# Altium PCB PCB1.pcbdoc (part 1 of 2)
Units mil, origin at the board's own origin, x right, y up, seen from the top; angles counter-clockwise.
Board outline 2869.57 x 2682.86 mil, 2 copper layers (Top Layer, Bottom Layer); 61 components, 43 nets, 230 pads, 47 vias.
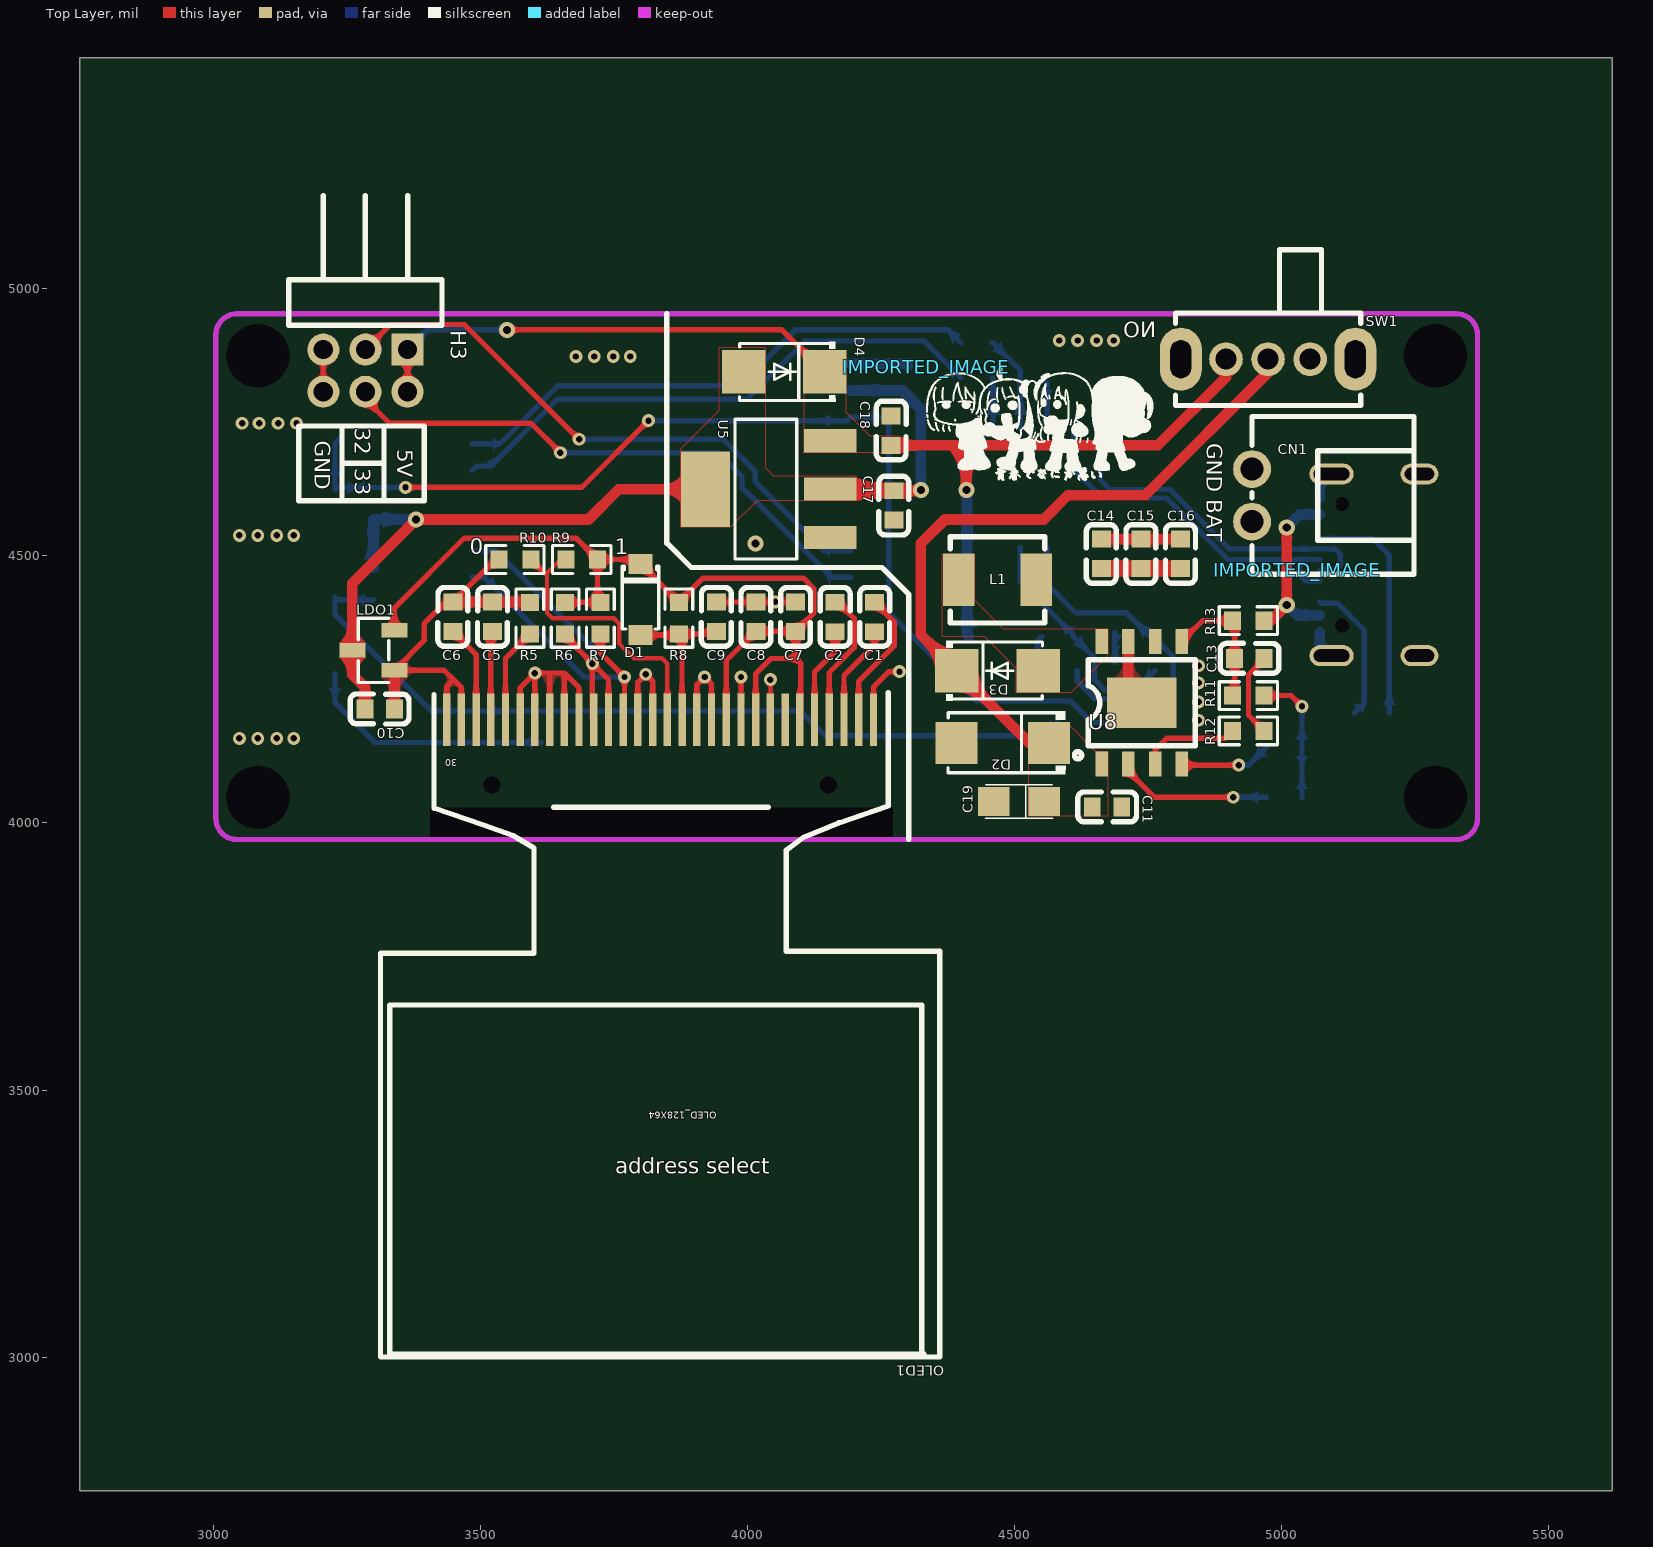
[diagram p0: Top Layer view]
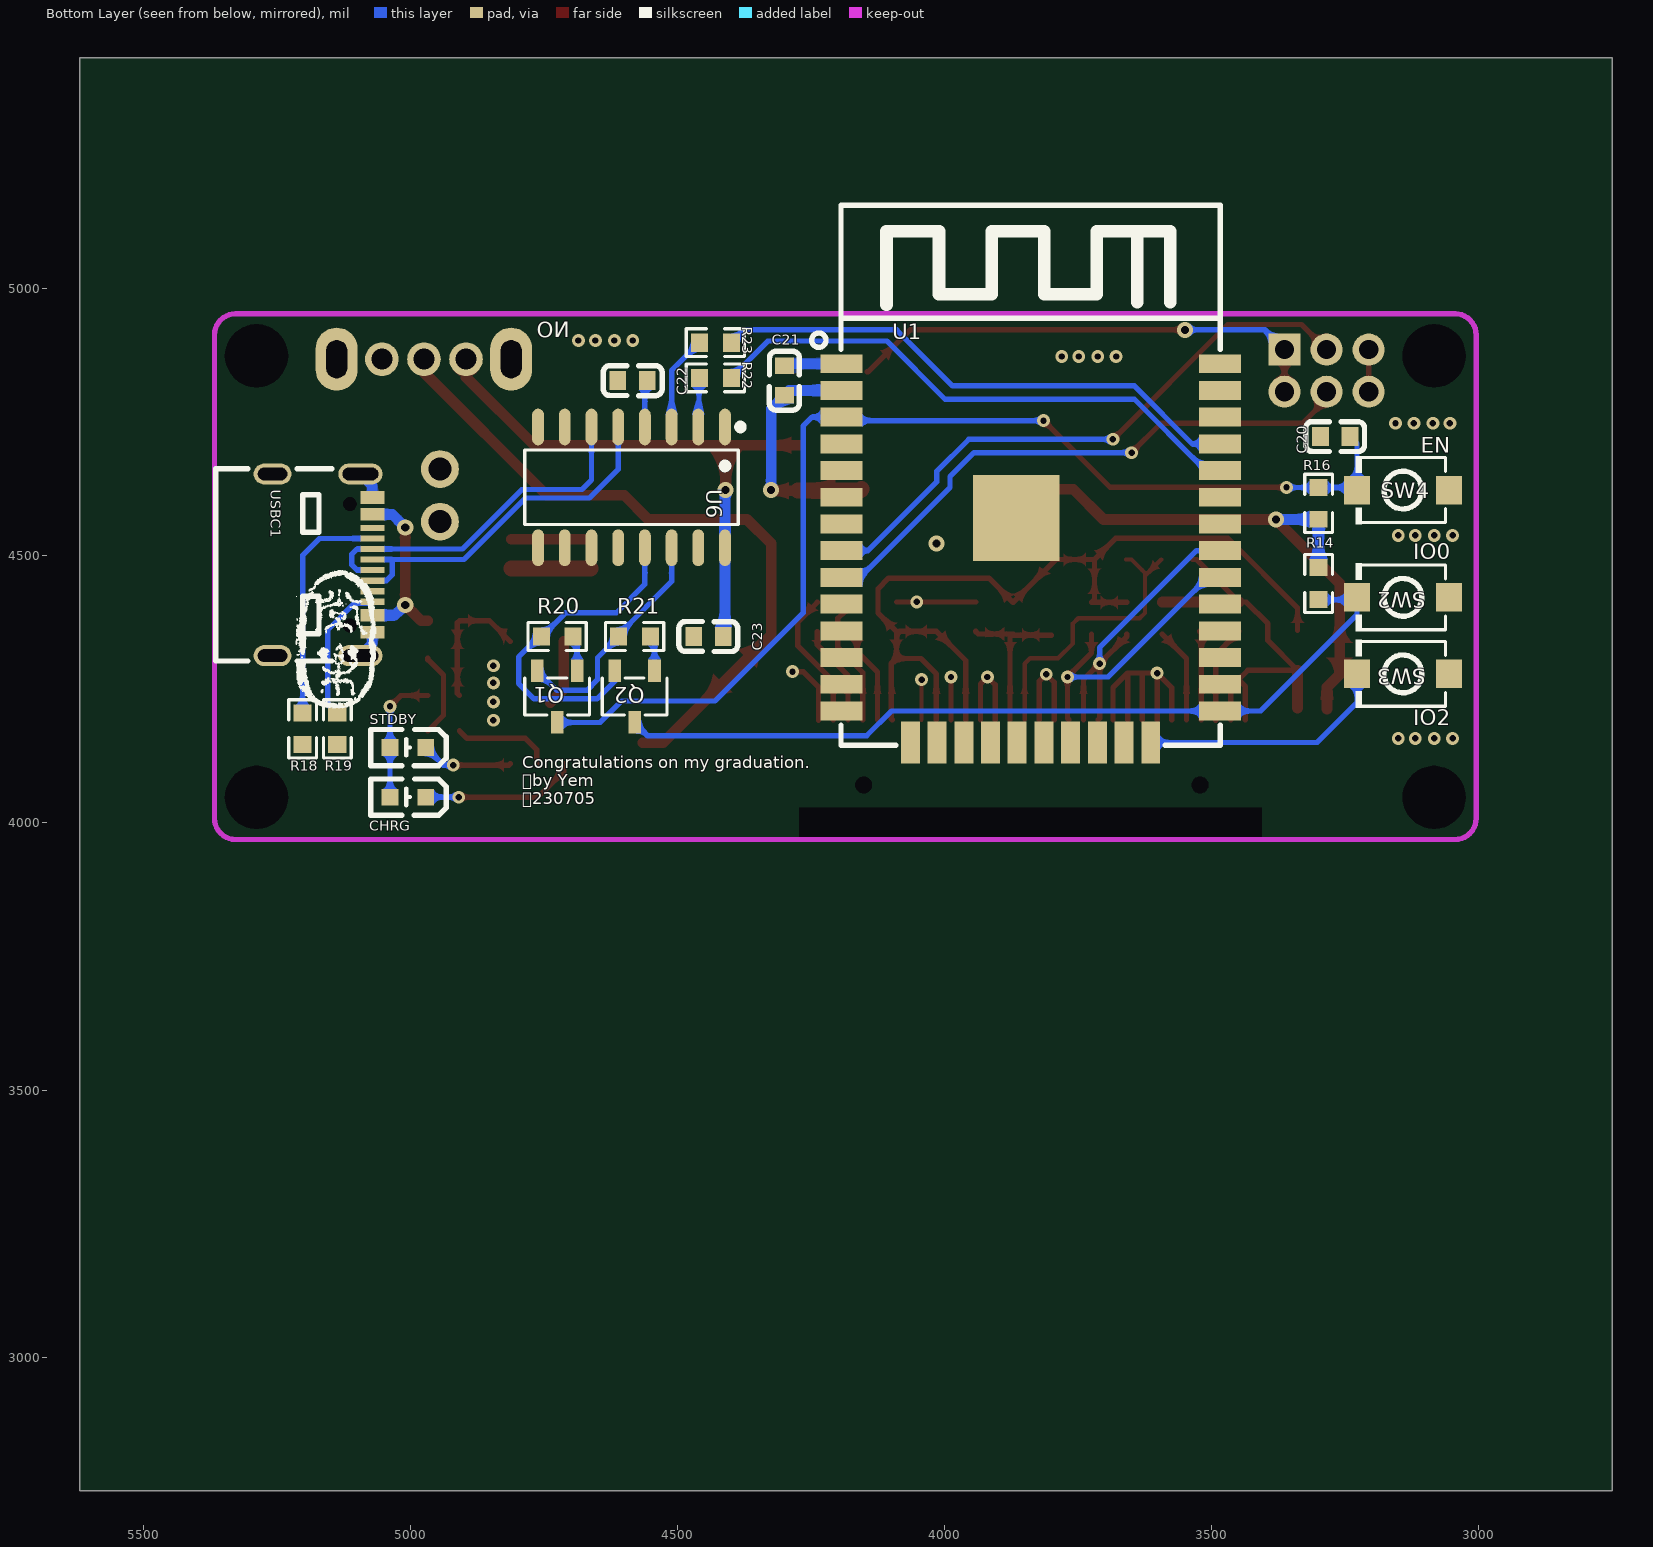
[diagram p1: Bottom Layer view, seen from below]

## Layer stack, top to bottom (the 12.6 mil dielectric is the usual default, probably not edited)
Top Layer: signal copper (thickness not stored)
Dielectric: dielectric 12.6, FR-4, Dk 4.8
Bottom Layer: signal copper (thickness not stored)

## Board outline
5619.57,2750 2750,2750 2750,5432.86 5619.57,5432.86
cut-out: 3142.8,4874.59 ccw(c3083.74,4874.59) 3024.69,4874.59 ccw(c3083.74,4874.59)
cut-out: 5347.52,4874.59 ccw(c5288.46,4874.59) 5229.41,4874.59 ccw(c5288.46,4874.59)
cut-out: 5347.52,4047.81 ccw(c5288.46,4047.81) 5229.41,4047.81 ccw(c5288.46,4047.81)
cut-out: 3142.8,4047.81 ccw(c3083.74,4047.81) 3024.69,4047.81 ccw(c3083.74,4047.81)
cut-out: 3406.18,3969.07 4272.32,3969.07 4272.32,4028.13 3406.18,4028.13

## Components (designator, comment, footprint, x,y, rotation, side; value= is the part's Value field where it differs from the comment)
C1 "1uf" C0603 4238.39,4385.65 r270 top
C2 "CAP_0603" C0603 4164.27,4385.65 r270 top
C5 "4.7uf" C0603 3523.01,4386.26 r90 top
C6 "2.2uf" C0603 3448.89,4386.26 r90 top
C7 "1uf" C0603 4090.36,4386.26 r90 top
C8 "1uf" C0603 4016.24,4386.26 r90 top
C9 "4.7uf" C0603 3942.12,4386.26 r90 top
C10 "1uf" C0603 3311.81,4213.33 r0 top
C11 "CAP_0603" C0603 4673.48,4030.14 r180 top
C13 "10uf" C0603 4939.99,4308.33 r180 top
C14 "0.1uf" C0603 4662.83,4503.89 r90 top
C15 "22uf" C0603 4736.95,4503.89 r90 top
C16 "22uf" C0603 4811.07,4503.89 r90 top
C17 "CAP_0603" C0603 4274.32,4594.53 r90 top
C18 "CAP_0603" C0603 4269.32,4734.53 r270 top
C19 "TC212A476K010Y" CASE-A_3216 4508.48,4040.14 r180 top
C20 "CAP_0603" C0603 3268.67,4723.33 r180 bottom
C21 "CAP_0603" C0603 4300,4828.33 r90 bottom
C22 "0.1uf" C0603 4584.42,4828.33 r0 bottom
C23 "CAP_0603" C0603 4442.28,4348.98 r180 bottom
CHRG "CHRG" LED0603-R-RD_GREEN 5005,4048.33 r0 bottom
CN1 "HX25003-2WAP" CONN-TH_2P-P2.50_HX25003-2WAP 4945,4613.33 r90 top
D1 "1N4148W_C2099" SOD-123_L2.8-W1.8-LS3.7-RD 3800,4418.33 r270 top
D2 "SMAJ6.0A_C223993" SMA_L4.3-W2.6-LS5.2-RD 4478.48,4150.14 r180 top
D3 "SS34-MS" DO-214AC_L4.3-W2.7-LS5.0-RD 4468.48,4285.14 r0 top
D4 "SS34-MS" DO-214AC_L4.3-W2.7-LS5.0-RD 4069.32,4844.53 r180 top
H3 "PZ200-2-03-W" HDR-TH_6P-P2.00-H-M-R2-C3-S2.00-W9.8 3285,4846.88 r180 top
IMPORTED_IMAGE "IMPORTED_IMAGE" IMPORTED_IMAGE 5030,4473.33 r0 top
IMPORTED_IMAGE "IMPORTED_IMAGE" IMPORTED_IMAGE 4335,4853.33 r0 top
L1 "TMPC0402HP-100MG-Z02" IND-SMD_L4.5-W4.1_TMPA0402SP 4468.48,4455.14 r0 top
LDO1 "SC662K-3.3V" SOT-23-3_L2.9-W1.3-P1.90-LS2.4-BR 3300,4323.33 r0 top
OLED1 "QG-2864KSWEG01" OLED-SMD_QG-2864KSWEG01 3836.77,4193.17 r180 top
Q1 "S8050_C105433" SOT-23-3_L2.9-W1.6-P1.90-LS2.8-BR 4725.66,4236.77 r90 bottom
Q2 "S8050_C105433" SOT-23-3_L2.9-W1.6-P1.90-LS2.8-BR 4580.66,4236.77 r90 bottom
R5 "910k" R0603 3592.97,4383.45 r270 top
R6 "4.7k" R0603 3658.98,4383.45 r270 top
R7 "4.7k" R0603 3725,4383.45 r270 top
R8 "4.7k" R0603 3871.94,4383.45 r90 top
R9 "4.7k" R0603 3690,4493.33 r0 top
R10 "4.7k" R0603 3565,4493.33 r0 top
R11 "1k" R0603 4938.02,4238.53 r180 top
R12 "3k" R0603 4938.02,4172.51 r180 top
R13 "0.3" R0603 4938.02,4378.66 r0 top
R14 "Res_0603" R0603 3300,4448.33 r90 bottom
R16 "Res_0603" R0603 3300,4598.33 r270 bottom
R18 "5K1" R0603 5202.18,4176.23 r90 bottom
R19 "5K1" R0603 5137.18,4176.23 r90 bottom
R20 "10k" R0603 4725.66,4349.09 r180 bottom
R21 "10k" R0603 4580.66,4349.09 r180 bottom
R22 "120" R0603 4429.22,4833.23 r0 bottom
R23 "120" R0603 4429.22,4899.24 r0 bottom
STDBY "TLMG1100-GS08" LED0603-R-RD_GREEN 5005,4141.14 r0 bottom
SW1 "SK12D07VG3" SW-TH_SK12D07VG3 4975,4868.33 r180 top
SW2 "TS-1088R-02026" SW-SMD_L3.9-W3.0-P4.45 3142.01,4422.43 r0 bottom
SW3 "TS-1088R-02026" SW-SMD_L3.9-W3.0-P4.45 3142.01,4279.12 r0 bottom
SW4 "TS-1088R-02026" SW-SMD_L3.9-W3.0-P4.45 3142.01,4623.33 r0 bottom
U1 "ESP32-WROOM-32-N4" WIFIM-SMD_ESP32-WROOM-32-N4 3839.25,4505.26 r180 bottom
U5 "AMS1117-3.3_C6186" SOT-223-3_L6.5-W3.4-P2.30-LS7.0-BR 4038.62,4625.04 r0 top
U6 "CH340C" SOP-16_L10.0-W3.9-P1.27-LS6.0-BL 4586.29,4628.33 r0 bottom
U8 "TP5400" ESOP-8_L4.9-W3.9-P1.27-LS6.0-BL-EP 4738.48,4225.14 r0 top
USBC1 "MC-311D" USB-C-SMD_MC-311D 5165,4483.33 r270 bottom

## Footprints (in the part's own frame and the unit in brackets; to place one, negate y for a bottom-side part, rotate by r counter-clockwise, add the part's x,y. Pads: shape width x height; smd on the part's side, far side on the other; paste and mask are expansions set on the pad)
C0603 [mm]
  rect 0.8x0.9 smd paste+0 mask+0.051: 1(-0.7,0) 2(0.7,0)
  silkscreen extent -1.41,-0.71 1.39,0.72
CASE-A_3216 [mil]
  rect 59.05x53.5 smd paste+0 mask+2: 1(-47.24,0) 2(47.24,0)
  silkscreen extent -63,-32 63,32
CONN-TH_2P-P2.50_HX25003-2WAP [mm]
  round 1.8 hole 1.1 paste+0 mask+0.051: 1(-1.25,0) 2(1.25,0)
  silkscreen extent -3.75,-7.7 3.75,0
DO-214AC_L4.3-W2.7-LS5.0-RD [mm]
  rect 2.07x2.06 smd paste+0 mask+0.051: 1(-1.929,0) 2(1.929,0)
  silkscreen extent -2.43,-1.43 2.14,1.43
ESOP-8_L4.9-W3.9-P1.27-LS6.0-BL-EP [mm]
  rect 0.6x1.2 smd paste+0 mask+0.051: 1(-1.905,-2.908) 2(-0.635,-2.908) 3(0.635,-2.908) 4(1.905,-2.908) 5(1.905,2.908) 6(0.635,2.908) 7(-0.635,2.908) 8(-1.905,2.908)
  rect 3.3x2.4 smd paste+0 mask+0.051: 9(0,0)
  silkscreen extent -3.2,-2.67 2.55,2.05
HDR-TH_6P-P2.00-H-M-R2-C3-S2.00-W9.8 [mil]
  rect 60x60 hole 36 mask+2: 1(-78.74,-39.37)
  round 60 hole 36 mask+2: 2(-78.74,39.37) 3(0,-39.37) 4(0,39.37) 5(78.74,-39.37) 6(78.74,39.37)
  silkscreen extent -143,-327 143,-85
IMPORTED_IMAGE [mil]
IND-SMD_L4.5-W4.1_TMPA0402SP [mm]
  rect 1.5x2.5 smd paste+0 mask+0.051: 1(-1.85,0) 2(1.85,0)
  silkscreen extent -2.25,-2.05 2.25,2.05
LED0603-R-RD_GREEN [mm]
  rect 0.8x0.8 smd paste+0 mask+0.051: 1(0.851,0) 2(-0.851,0)
  silkscreen extent -1.82,-0.86 1.77,0.86
OLED-SMD_QG-2864KSWEG01 [mil]
  rect 13.8x98.4 smd paste+0 mask+1.97: 1(-399.57,-0.09) 2(-371.81,-0.01) 3(-344.25,-0.01) 4(-316.69,-0.01) 5(-289.13,-0.01) 6(-261.57,-0.01) 7(-234.01,-0.01) 8(-206.46,-0.01) 9(-178.9,-0.01) 10(-151.34,-0.01) 11(-123.78,-0.01) 12(-96.22,-0.01) 13(-68.66,-0.01) 14(-41.1,-0.01) 15(-13.54,-0.01) 16(14.02,-0.01) 17(41.58,-0.01) 18(69.13,-0.01) 19(96.69,-0.01) 20(124.25,-0.01) 21(151.81,-0.01) 22(179.37,-0.01) 23(206.93,-0.01) 24(234.49,-0.01) 25(262.05,-0.01) 26(289.61,-0.01) 27(317.17,-0.01) 28(344.53,0.05) 29(372.05,0.09) 30(399.57,0.09)
  Multi-Layer board cut-out: -330.71,122.05 -329.15,115.22 -324.78,109.74 -318.46,106.7 -311.46,106.7 -305.14,109.74 -300.77,115.22 -299.21,122.05 -299.21,122.05 -300.77,128.88 -305.14,134.36 -311.46,137.4 -318.46,137.4 -324.78,134.36 -329.15,128.88 -330.71,122.05
  Multi-Layer board cut-out: 299.21,122.05 300.77,115.22 305.14,109.74 311.46,106.7 318.46,106.7 324.78,109.74 329.15,115.22 330.71,122.05 330.71,122.05 329.15,128.88 324.78,134.36 318.46,137.4 311.46,137.4 305.14,134.36 300.77,128.88 299.21,122.05
  silkscreen extent -524,-51 524,1193
R0603 [mil]
  rect 31.75x34.02 smd paste-3937.01 mask+2: 1(-29.66,0) 2(29.66,0)
  silkscreen extent -55,-26 55,26
SMA_L4.3-W2.6-LS5.2-RD [mm]
  rect 2x2 smd paste+0 mask+0.051: 1(-2.2,0) 2(2.2,0)
  silkscreen extent -2.98,-1.5 2.6,1.5
SOD-123_L2.8-W1.8-LS3.7-RD [mm]
  rect 0.95x1.15 smd paste+0 mask+0.051: 1(-1.692,0) 2(1.692,0)
  silkscreen extent -1.58,-0.87 1.41,0.87
SOP-16_L10.0-W3.9-P1.27-LS6.0-BL [mm]
  oval 0.56x1.745 smd paste+0 mask+0.051: 1(-4.445,-2.872) 2(-3.175,-2.872) 3(-1.905,-2.872) 4(-0.635,-2.872) 5(0.635,-2.872) 6(1.905,-2.872) 7(3.175,-2.872) 8(4.445,-2.872) 9(4.445,2.872) 10(3.175,2.872) 11(1.905,2.872) 12(0.635,2.872) 13(-0.635,2.872) 14(-1.905,2.872) 15(-3.175,2.872) 16(-4.445,2.872)
  silkscreen extent -5.33,-3.02 5.08,1.77
SOT-23-3_L2.9-W1.3-P1.90-LS2.4-BR [mm]
  rect 1.25x0.7 smd paste+0 mask+0.051: 1(1,-0.95) 2(1,0.95) 3(-1,0)
  silkscreen extent -0.73,-1.53 0.73,1.53
SOT-23-3_L2.9-W1.6-P1.90-LS2.8-BR [mm]
  rect 1.07x0.6 smd paste+0 mask+0.051: 1(1.235,-0.95) 2(1.235,0.95) 3(-1.235,0)
  silkscreen extent -0.88,-1.54 0.88,1.54
SOT-223-3_L6.5-W3.4-P2.30-LS7.0-BR [mm]
  rect 2.5x1.1 smd paste+0 mask+0.051: 1(2.97,-2.3) 2(2.97,0) 3(2.97,2.3)
  rect 2.34x3.6 smd paste+0 mask+0.051: 4(-2.97,0)
  silkscreen extent -1.57,-3.33 1.37,3.33
SW-SMD_L3.9-W3.0-P4.45 [mm]
  rect 1.23x1.36 smd paste+0 mask+0.051: 1(-2.185,0) 2(2.185,0)
  silkscreen extent -2.03,-1.62 2.25,1.62
SW-TH_SK12D07VG3 [mm]
  round 1.6 hole 1 paste+0 mask+0.051: 1(-2,0) 2(0,0) 3(2,0)
  oval 2x3 hole 1 slot 1.8 at 90 deg paste+0 mask+0.051: 4(4.15,0) 5(-4.15,0)
  silkscreen extent -4.4,-5.2 4.4,2.2
USB-C-SMD_MC-311D [mm]
  oval 1x2.1 hole 0.6 slot 1.7 at 90 deg paste+0 mask+0.05: 1(-4.32,1.808) 4(4.32,1.807)
  oval 1x1.8 hole 0.6 slot 1.4 at 90 deg paste+0 mask+0.05: 2(-4.32,-2.372) 3(4.32,-2.373)
  rect 0.6x1.15 smd paste-100 mask+0.05: A1-B12(-3.2,2.372) A4-B9(-2.4,2.372) B1-A12(3.2,2.372) B4-A9(2.4,2.372)
  rect 0.3x1.15 smd paste-100 mask+0.05: A5(-1.25,2.372) A6(-0.25,2.372) A7(0.25,2.372) A8(1.25,2.372) B5(1.75,2.372) B6(0.75,2.372) B7(-0.75,2.372) B8(-1.75,2.372)
  Multi-Layer board cut-out: 2.89,0.982 2.749,1.015 2.636,1.105 2.573,1.235 2.573,1.38 2.636,1.51 2.749,1.6 2.89,1.632 2.89,1.632 3.031,1.6 3.144,1.51 3.207,1.38 3.207,1.235 3.144,1.105 3.031,1.015 2.89,0.982
  Multi-Layer board cut-out: -2.89,0.982 -3.031,1.015 -3.144,1.105 -3.207,1.235 -3.207,1.38 -3.144,1.51 -3.031,1.6 -2.89,1.632 -2.89,1.632 -2.749,1.6 -2.636,1.51 -2.573,1.38 -2.573,1.235 -2.636,1.105 -2.749,1.015 -2.89,0.982
  silkscreen extent -4.57,-5.08 4.57,0.44
WIFIM-SMD_ESP32-WROOM-32-N4 [mm]
  rect 2x0.9 smd paste+0 mask+0.05: 1(-9,9.005) 2(-9,7.735) 3(-9,6.465) 4(-9,5.195) 5(-9,3.925) 6(-9,2.655) 7(-9,1.385) 8(-9,0.115) 9(-9,-1.155) 10(-9,-2.425) 11(-9,-3.695) 12(-9,-4.965) 13(-9,-6.235) 14(-9,-7.505) 25(9,-7.505) 26(9,-6.235) 27(9,-4.965) 28(9,-3.695) 29(9,-2.425) 30(9,-1.155) 31(9,0.115) 32(9,1.385) 33(9,2.655) 34(9,3.925) 35(9,5.195) 36(9,6.465) 37(9,7.735) 38(9,9.005)
  rect 0.9x2 smd paste+0 mask+0.05: 15(-5.715,-9.005) 16(-4.445,-9.005) 17(-3.175,-9.005) 18(-1.905,-9.005) 19(-0.635,-9.005) 20(0.635,-9.005) 21(1.905,-9.005) 22(3.175,-9.005) 23(4.445,-9.005) 24(5.715,-9.005)
  rect 4.1x4.1 smd paste+0 mask+0.05: 39(-0.68,1.665)
  silkscreen extent -10.41,-9.13 9.02,16.54

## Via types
v1: diameter 24, hole 12, Top Layer to Bottom Layer, 40 vias
v2: diameter 30, hole 15, Top Layer to Bottom Layer, 7 vias

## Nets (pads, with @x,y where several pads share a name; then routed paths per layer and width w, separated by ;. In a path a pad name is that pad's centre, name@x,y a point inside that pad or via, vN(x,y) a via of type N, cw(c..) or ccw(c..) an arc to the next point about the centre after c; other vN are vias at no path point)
3V3: C10.1 C17.2 C21.1 D4.2 LDO1.3 R14.2 R16.2 U1.2 U5.2 U5.4 | length 1619.4
  Top Layer w20: C10.1@3284.25,4213.33 3284.25,4254.08 3260.63,4277.7 LDO1.3@3260.63,4323.33 3260.63,4448.96 v2(3380,4568.33) 3702.75,4568.33 3759.47,4625.04 U5.4@3921.69,4625.04 ; C17.2@4274.32,4622.09 4323.77,4622.09 v2(4325,4623.33)
  Top Layer w30: U5.2@4155.55,4625.04 4158.49,4622.09 C17.2@4274.32,4622.09
  Bottom Layer w20: R14.2@3300,4477.99 R16.2@3300,4568.67 3300.34,4568.33 v2(3380,4568.33) ; U1.2@4193.58,4809.79 4290.98,4809.79 C21.1@4300,4800.77 4325,4775.77 v2(4325,4623.33)
$1N1215: C1.1 OLED1.2 | length 262.4
  Top Layer w10: OLED1.2@4208.58,4193.49 4208.58,4265 4275,4331.42 4275,4376.6 C1.1@4238.39,4413.21
$1N1238: C2.1 OLED1.4 | length 257.2
  Top Layer w10: OLED1.4@4153.46,4193.49 4153.46,4281.79 4200,4328.33 4200,4383.33 4170.12,4413.21 C2.1@4164.27,4413.21
$1N1393: C1.2 OLED1.3 | length 188.4
  Top Layer w10: OLED1.3@4181.02,4193.49 4181.02,4275.72 4238.39,4333.09 C1.2@4238.39,4358.09
$1N1397: C2.2 OLED1.5 | length 180.5
  Top Layer w10: OLED1.5@4125.9,4193.49 4125.9,4282.51 4164.27,4320.88 C2.2@4164.27,4358.09
$1N1534: OLED1.26 R5.2 | length 179.3
  Top Layer w10: OLED1.26@3547.16,4193.49 3547.16,4307.99 R5.2@3592.97,4353.79
$1N1817: C5.1 OLED1.27 | length 166.6
  Top Layer w10: OLED1.27@3519.6,4193.49 3519.6,4355.29 C5.1@3523.01,4358.7
$1N1822: C6.1 OLED1.28 | length 184.2
  Top Layer w10: C6.1@3448.89,4358.7 3492.24,4315.34 OLED1.28@3492.24,4192.49
$1N3071: C9.1 D1.2 OLED1.14 R8.1 | length 307.8
  Top Layer w10: D1.2@3800,4351.7 3869.84,4351.7 R8.1@3871.94,4353.79 ; OLED1.14@3877.87,4193.49 3877.87,4347.86 R8.1@3871.94,4353.79 ; C9.1@3942.12,4358.7 3937.21,4353.79 R8.1@3871.94,4353.79
$1N3221: OLED1.15 R9.1 R10.2 | length 554.8
  Top Layer w8: R10.2@3594.66,4493.33 3625,4462.99 ; R9.1@3660.34,4493.33 3650.34,4493.33 3625,4467.99 3625,4462.99 ; OLED1.15@3850.31,4193.18 3850.31,4298.01 3840,4308.33 3787.89,4308.33 3760,4336.22 3760,4373.33 3750,4383.33 3635,4383.33 3625,4393.33 3625,4462.99
$1N4369: CHRG.2 U8.2 | length 292.1
  Top Layer w10: U8.2@4713.48,4110.64 4713.48,4096.5 4761.65,4048.33 v1(4910,4048.33)
  Bottom Layer w10: v1(4910,4048.33) CHRG.2@4971.5,4048.33
$1N4372: STDBY.2 U8.4 | length 172.6
  Top Layer w10: U8.4@4813.48,4110.64 4815.79,4108.33 v1(4920,4108.33)
  Bottom Layer w10: v1(4920,4108.33) 4938.69,4108.33 STDBY.2@4971.5,4141.14
$1N4419: CHRG.1 R11.1 STDBY.1 | length 249.2
  Top Layer w10: R11.1@4967.68,4238.53 5018.3,4238.53 v1(5038.5,4218.33)
  Bottom Layer w10: CHRG.1@5038.5,4048.33 STDBY.1@5038.5,4141.14 v1(5038.5,4218.33)
$1N4498: D3.2 L1.1 U8.8
$1N9366: R18.2 USBC1.A5 | length 438.8
  Bottom Layer w10: USBC1.A5@5071.6,4532.54 5170.79,4532.54 5202.18,4501.15 R18.2@5202.18,4205.89
$1N9477: C22.1 U6.4 | length 88.7
  Bottom Layer w10: C22.1@4556.86,4828.33 4561.29,4823.89 U6.4@4561.29,4741.42
$1N9678: Q2.1 R21.2 | length 66.9
  Bottom Layer w10: Q2.1@4543.26,4285.39 4543.26,4341.35 R21.2@4551,4349.09
$1N9680: Q1.1 R20.2 | length 66.9
  Bottom Layer w10: Q1.1@4688.26,4300.39 R20.2@4688.26,4341.35 ; R20.2@4688.26,4356.35 R20.2@4688.26,4341.35 ; R20.2@4696,4349.09 R20.2@4688.26,4341.35
$1N9758: R22.2 U6.2 | length 92.8
  Bottom Layer w10: R22.2@4458.88,4833.23 4460,4832.11 4460,4742.71 U6.2@4461.29,4741.42
$1N9782: R23.2 U6.3 | length 179.5
  Bottom Layer w10: R23.2@4458.88,4899.24 4511.29,4846.83 U6.3@4511.29,4741.42
$1N12007: R12.2 U8.3 | length 185.8
  Top Layer w10: U8.3@4763.48,4110.64 4763.48,4136.81 4785,4158.33 4894.18,4158.33 R12.2@4908.36,4172.51
$1N12056: C13.2 R11.2 R13.1 U8.5 | length 254.6
  Top Layer w10: U8.5@4813.48,4339.64 4852.5,4378.66 R13.1@4908.36,4378.66 4912.43,4374.59 C13.2@4912.43,4308.33 4912.43,4242.6 R11.2@4908.36,4238.53
$1N17323: R19.2 USBC1.B5 | length 268.5
  Bottom Layer w10: USBC1.B5@5071.6,4414.43 5074.37,4411.65 5105.08,4411.65 5155,4361.72 5155,4223.71 R19.2@5137.18,4205.89
+5V: C18.2 C23.2 D4.1 H3.1 H3.2 SW1.3 U5.3 U6.16 | length 1981.7
  Top Layer w10: H3.2@3363.74,4807.51 H3.1@3363.74,4886.25 ; v2(3550,4923.33) 4065,4923.33 4143.79,4844.53 D4.1@4145.27,4844.53
  Top Layer w20: C18.2@4269.32,4706.97 4410,4706.97 ; v2(4410,4623.33) 4410,4706.97 ; SW1.3@4896.26,4868.33 4896.26,4834.59 4768.65,4706.97 4410,4706.97
  Bottom Layer w10: H3.1@3363.74,4886.25 3400.82,4923.33 v2(3550,4923.33)
  Bottom Layer w20: v2(4410,4623.33) 4411.29,4622.03 U6.16@4411.29,4515.24 4411.29,4352.41 C23.2@4414.72,4348.98
BAT: C14.1 C15.1 C16.1 CN1.1 L1.2 U8.6 | length 148.2
  Top Layer w30: C14.1@4662.83,4476.33 C15.1@4736.95,4476.33 C16.1@4811.07,4476.33
D+: U6.5 USBC1.A6 USBC1.B6 | length 680
  Bottom Layer w10: U6.5@4611.29,4741.42 4611.29,4662.03 4665,4608.33 4785,4608.33 4900.16,4493.17 5034.47,4493.17 ; USBC1.B6@5071.6,4453.8 5045,4453.8 5034.47,4464.33 5034.47,4493.17 ; USBC1.A6@5071.6,4493.17 5034.47,4493.17
D-: U6.6 USBC1.A7 USBC1.B7 | length 668
  Bottom Layer w10: U6.6@4661.29,4741.42 4661.29,4642.03 4679,4624.33 4791.63,4624.33 4903.1,4512.86 USBC1.B7@5071.6,4512.86 5100.47,4512.86 5110,4503.33 5110,4483.33 5100.16,4473.49 USBC1.A7@5071.6,4473.49
DTR: Q2.2 R20.1 U6.13 | length 636
  Bottom Layer w10: U6.13@4561.29,4515.24 4561.29,4447.03 4615,4393.33 4710,4393.33 4754.24,4349.09 R20.1@4755.32,4349.09 4759.24,4349.09 4797.67,4310.66 4797.67,4261 4769,4232.33 4651,4232.33 4618.06,4265.26 Q2.2@4618.06,4285.39
EN: C20.2 Q1.3 R16.1 SW4.2 U1.3 | length 2101.4
  Top Layer w10: v1(3360,4628.33) 3690,4628.33 v1(3815,4753.33)
  Bottom Layer w10: C20.2@3241.11,4723.33 3228.03,4710.25 SW4.2@3228.03,4623.33 3232.69,4627.99 R16.1@3300,4627.99 3359.66,4627.99 v1(3360,4628.33) ; v1(3815,4753.33) 4187.12,4753.33 U1.3@4193.58,4759.79 4248.54,4759.79 4265,4743.33 4265,4393.33 4430,4228.33 4605,4228.33 4645.19,4188.14 Q1.3@4725.66,4188.14
GND: C5.2 C6.2 C7.2 C8.2 C9.2 C10.2 C11.1 C13.1 C14.2 C15.2 C16.2 C17.1 C18.1 C19.2 C20.1 C21.2 C22.2 C23.1 CN1.2 D2.2 H3.5 H3.6 LDO1.1 OLED1.1 OLED1.8 OLED1.10 OLED1.12 OLED1.13 OLED1.16 OLED1.17 OLED1.21 OLED1.22 OLED1.23 OLED1.24 OLED1.25 OLED1.29 OLED1.30 R5.1 R10.1 R12.1 R18.1 R19.1 SW2.1 SW3.1 SW4.1 U1.1 U1.38 U1.39 U5.1 U6.1 U8.7 U8.9 USBC1.1 USBC1.2 USBC1.3 USBC1.4 USBC1.A1-B12 USBC1.B1-A12 | length 2823.8
  Top Layer w8: OLED1.8@4043.23,4193.18 v1(4043.23,4268.33)
  Top Layer w10: H3.6@3206.26,4807.51 H3.5@3206.26,4886.25 ; OLED1.30@3437.2,4193.08 3437.2,4255.53 3450,4268.33 ; OLED1.29@3464.72,4193.08 3464.72,4253.6 3450,4268.33 ; C5.2@3523.01,4413.82 C5.2@3527.21,4418.02 ; R10.1@3535.34,4493.33 3528.39,4493.33 C6.2@3448.89,4413.82 3435.49,4413.82 3395,4373.33 3395,4341.56 LDO1.1@3339.37,4285.93 3432.4,4285.93 3450,4268.33 ; OLED1.25@3574.72,4193.18 3574.72,4253.05 v1(3602.28,4280.61) ; OLED1.24@3602.28,4193.18 v1(3602.28,4280.61) ; OLED1.23@3629.84,4193.18 3629.84,4279.61 3631.06,4280.83 ; OLED1.22@3657.4,4193.18 3657.4,4280.73 3657.5,4280.83 ; OLED1.21@3684.96,4193.18 3684.96,4253.36 3657.5,4280.83 ; OLED1.17@3795.19,4193.18 3795.19,4263.52 v1(3810,4278.33) 3822.75,4265.57 OLED1.16@3822.75,4193.18 ; OLED1.13@3905.43,4193.18 3905.43,4258.76 v1(3920,4273.33) 3932.99,4260.33 OLED1.12@3932.99,4193.18 ; C9.2@3942.12,4413.82 C8.2@4016.24,4413.82 v1(4052.35,4413.82) C7.2@4090.36,4413.82 ; OLED1.10@3988.11,4193.18 v1(3988.11,4273.33) ; OLED1.1@4236.34,4192.63 4236.34,4254.67 4265,4283.33 v1(4285,4283.33) ; C13.1@4967.55,4308.33 4967.55,4305.88 4938.48,4276.81 4938.48,4201.71 R12.1@4967.68,4172.51 ; v1(3602.28,4280.61) 3602.5,4280.83 3631.06,4280.83 ; 3631.06,4280.83 3657.5,4280.83
  Top Layer w20: C10.2@3339.37,4215.14 LDO1.1@3339.37,4285.93 ; C6.2@3448.89,4413.82 C5.2@3523.01,4413.82 3592.26,4413.82 R5.1@3592.97,4413.11 ; C14.2@4662.83,4531.45 C15.2@4736.95,4531.45 C16.2@4811.07,4531.45 ; U8.7@4713.48,4339.64 4713.48,4250.14 U8.9@4738.48,4225.14
  Bottom Layer w20: U1.1@4193.58,4859.79 4296.1,4859.79 C21.2@4300,4855.89 ; USBC1.B1-A12@5071.6,4357.35 5071.6,4335.49 USBC1.4@5093.84,4313.25 ; USBC1.A1-B12@5071.6,4609.32 5071.6,4631.17 USBC1.1@5093.84,4653.41
  other v1: 3049.11,4158.33 3083.45,4158.33 3119.01,4158.33 3150.89,4158.33 4845,4192.44 4845,4226.77 4845,4262.33 4845,4294.21 3049.11,4538.33 3083.45,4538.33 3119.01,4538.33 3150.89,4538.33 3054.11,4748.33 3085.99,4748.33 3121.55,4748.33 3155.89,4748.33 3679.11,4873.33 3713.45,4873.33 3749.01,4873.33 3780.89,4873.33 4584.11,4903.33 4618.45,4903.33 4654.01,4903.33 4685.89,4903.33
  other v2: 4015,4523.33
IO0: Q2.3 R14.1 SW2.2 U1.25 | length 1562.9
  Bottom Layer w10: R14.1@3300,4417.99 3232.47,4417.99 SW2.2@3228.03,4422.43 3228.03,4390.29 3408.54,4209.79 U1.25@3484.92,4209.79 4099.59,4209.79 4146.05,4163.33 4555.85,4163.33 Q2.3@4580.66,4188.14
IO2: SW3.2 U1.24 | length 470.9
  Bottom Layer w10: SW3.2@3228.03,4279.12 3228.03,4225.29 3302.6,4150.73 U1.24@3614.25,4150.73
IO32: H3.3 U1.8 | length 1115.2
  Top Layer w10: H3.3@3285,4886.25 3332.08,4933.33 3470,4933.33 v1(3685,4718.33)
  Bottom Layer w10: v1(3685,4718.33) 3955,4718.33 4015,4658.33 4015,4638.33 4143.54,4509.79 U1.8@4193.58,4509.79
IO33: H3.4 U1.9 | length 1072.6
  Top Layer w10: H3.4@3285,4807.51 3285,4793.33 3330,4748.33 3595,4748.33 v1(3650,4693.33)
  Bottom Layer w10: v1(3650,4693.33) 3945,4693.33 3990,4648.33 3990,4628.33 4158.54,4459.79 U1.9@4193.58,4459.79
RTS: Q1.2 R21.1 U6.14 | length 441.1
  Bottom Layer w10: U6.14@4511.29,4515.24 4511.29,4452.03 4610.32,4353 R21.1@4610.32,4349.09 4650,4309.41 4650,4268.33 4670,4248.33 4726,4248.33 Q1.2@4763.06,4285.39
RXD0: R22.1 U1.34 | length 1044
  Bottom Layer w10: U1.34@3484.92,4659.79 3493.46,4668.33 3520,4668.33 3645,4793.33 3999.27,4793.33 4108.27,4902.33 4331,4902.33 4399.56,4833.77 R22.1@4399.56,4833.23
SCL: OLED1.18 R7.2 U1.30 | length 542.2
  Top Layer w10: R7.2@3725,4353.79 3725,4318.33 v1(3770,4273.33) 3770,4195.85 OLED1.18@3767.64,4193.49
  Bottom Layer w10: U1.30@3484.92,4459.79 3507.57,4459.79 3694.03,4273.33 v1(3770,4273.33)
SDA: OLED1.19 OLED1.20 R6.2 U1.31 | length 630.6
  Top Layer w10: R6.2@3658.98,4353.79 3658.98,4349.34 v1(3710,4298.33) ; OLED1.20@3712.52,4193.18 3710,4195.7 v1(3710,4298.33) ; OLED1.19@3740.08,4193.18 3740.08,4268.24 v1(3710,4298.33)
  Bottom Layer w10: U1.31@3484.92,4509.79 3528.54,4509.79 3710,4328.33 v1(3710,4298.33)
TXD0: R23.1 U1.35 | length 1013.1
  Bottom Layer w10: U1.35@3484.92,4709.79 3536.46,4709.79 3645,4818.33 3985,4818.33 4090,4923.33 4375.48,4923.33 R23.1@4399.56,4899.24
V_USB: R13.2 USBC1.A4-B9 USBC1.B4-A9 | length 341
  Top Layer w20: R13.2@4967.68,4378.66 4980.34,4378.66 v2(5010,4408.33) v2(5010,4553.33)
  Bottom Layer w20: v2(5010,4408.33) 5029.49,4388.84 USBC1.B4-A9@5071.6,4388.84 ; v2(5010,4553.33) 5034.49,4577.82 USBC1.A4-B9@5071.6,4577.82
VCC: C7.1 C8.1 D1.1 LDO1.2 OLED1.6 OLED1.9 OLED1.11 R6.1 R7.1 R8.2 R9.2 | length 1808.2
  Top Layer w10: LDO1.2@3339.37,4360.73 3339.37,4402.7 3470,4533.33 3679.66,4533.33 R9.2@3719.66,4493.33 ; R6.1@3658.98,4413.11 R7.1@3725,4413.11 3719.66,4418.45 R9.2@3719.66,4493.33 ; OLED1.11@3960.55,4193.49 3960.55,4303.88 4015.37,4358.7 C8.1@4016.24,4358.7 4084.73,4358.7 C7.1@4090.36,4353.07 ; OLED1.9@4015.67,4193.49 4015.67,4279 4044.64,4307.97 4090.36,4307.97 ; OLED1.6@4098.34,4193.49 4100,4195.15 4100,4298.33 4090.36,4307.97 ; R9.2@3719.66,4493.33 3791.63,4493.33 D1.1@3800,4484.96 3800.1,4484.96 R8.2@3871.94,4413.11 3917.15,4458.33 4105,4458.33 4125,4438.33 4125,4393.34 C7.1@4090.36,4358.7 C7.1@4090.36,4353.07 ; 4090.36,4307.97 C7.1@4090.36,4353.07
VOUT: C11.2 C19.1 D2.1 D3.1 SW1.2 U8.1 | length 1302.2
  Top Layer w20: D2.1@4565.09,4150.14 4527.53,4150.14 D3.1@4392.53,4285.14 4325,4352.67 4325,4523.33 4370,4568.33 4555,4568.33 4600,4613.33 4745,4613.33 4975,4843.33 SW1.2@4975,4868.33
"": OLED1.7 SW1.1 SW1.4 SW1.5 U1.4 U1.5 U1.6 U1.7 U1.10 U1.11 U1.12 U1.13 U1.14 U1.15 U1.16 U1.17 U1.18 U1.19 U1.20 U1.21 U1.22 U1.23 U1.26 U1.27 U1.28 U1.29 U1.32 U1.33 U1.36 U1.37 U6.7 U6.8 U6.9 U6.10 U6.11 U6.12 U6.15 USBC1.A8 USBC1.B8

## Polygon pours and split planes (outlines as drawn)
+5V on Top Layer (solid, remove dead copper, pour order 0): 4184.32,4884.53 4184.32,4769.53 4229.32,4724.53 4285.07,4724.53 4285.07,4693.38 4104.32,4693.38 4106.49,4695.55 4106.49,4884.01 4107.02,4884.53
3V3 on Top Layer (solid, remove dead copper, pour order 1): 4204.32,4649.53 4049.32,4649.53 4034.32,4664.53 4034.32,4889.53 3946.97,4889.53 3946.97,4772.18 3874.32,4699.53 3874.32,4554.53 3969.32,4554.53 4019.32,4604.53 4204.32,4604.53
VOUT on Top Layer (solid, remove dead copper, pour order 2): 4674.75,4012.33 4527.06,4012.33 4527.06,4188.17 4598.3,4188.17 4651.88,4134.59 4674.75,4134.59
BAT on Top Layer (solid, remove dead copper, pour order 3): 4510.81,4503.59 4857.59,4503.59 4900,4545.99 4900,4583.33 4924.27,4607.6 4983.5,4607.6 4983.5,4546.82 4870,4433.33 4835,4433.33 4780,4378.33 4780,4314.42 4743.04,4314.42 4743.04,4380.29 4720,4403.33 4510,4403.33 4510.81,4404.14
$1N4498 on Top Layer (solid, remove dead copper, pour order 4): 4365,4503.33 4425,4503.33 4425,4417.57 4479.24,4363.33 4675,4363.33 4675,4313.33 4605.22,4243.55 4503.52,4243.55 4503.52,4289.8 4445,4348.33 4365,4348.33
GND on Bottom Layer (solid, remove dead copper, pour order 5): 5365,4958.33 3027.33,4958.33 3002.33,4933.33 3002.33,3971 3010,3963.33 5365,3963.33
GND on Top Layer (solid, remove dead copper, pour order 6): 3000,4958.33 3820,4958.33 3851.02,4927.3 3851.02,4480.44 4249.92,4480.44 4285.22,4445.14 4285.22,3963.33 3000,3963.33
GND on Top Layer (solid, remove dead copper, pour order 7): 3875.76,4953.33 5369.57,4953.33 5369.57,3958.33 4315,3958.33 4315,4458.33 4280,4493.33 3875,4493.33 3875,4952.57

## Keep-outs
Board Outline Layer:
  lines w10 net "": 3005,4008.44 ccw(c3044.37,4008.44) 3044.37,3969.07 5327.83,3969.07 ccw(c5327.83,4008.44) 5367.2,4008.44 5367.2,4913.96 ccw(c5327.83,4913.96) 5327.83,4953.33 3044.37,4953.33 ccw(c3044.37,4913.96) 3005,4913.96 3005,4008.44

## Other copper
Top Layer:
  region net $1N1215: 4213.58,4257.38 4203.58,4257.38 cw(c4143.42,4257.38) 4201.68,4242.38 4215.48,4242.38 cw(c4273.74,4257.38)
  region net $1N1393: 4186.02,4257.38 4176.02,4257.38 cw(c4115.86,4257.38) 4174.12,4242.38 4187.92,4242.38 cw(c4246.18,4257.38)
  region net $1N1238: 4158.46,4257.38 4148.46,4257.38 cw(c4088.3,4257.38) 4146.56,4242.38 4160.36,4242.38 cw(c4218.62,4257.38)
  region net $1N1397: 4130.9,4257.38 4120.9,4257.38 cw(c4060.74,4257.38) 4119,4242.38 4132.8,4242.38 cw(c4191.06,4257.38)
  region net VCC: 4105,4257.38 4095,4257.38 cw(c4061.6,4257.38) 4091.44,4242.38 4105.24,4242.38 cw(c4570.57,4257.38)
  region net VCC: 4020.67,4257.38 4010.67,4257.38 cw(c3950.51,4257.38) 4008.77,4242.38 4022.57,4242.38 cw(c4080.83,4257.38)
  region net VCC: 3965.55,4257.38 3955.55,4257.38 cw(c3895.39,4257.38) 3953.65,4242.38 3967.45,4242.38 cw(c4025.71,4257.38)
  region net $1N3071: 3882.87,4257.38 3872.87,4257.38 cw(c3765.68,4257.38) 3871.82,4242.38 3883.93,4242.38 cw(c3990.07,4257.38)
  region net $1N3221: 3854.31,4254.38 3846.31,4254.38 cw(c3820.03,4254.38) 3843.41,4242.38 3857.21,4242.38 cw(c3880.59,4254.38)
  region net SDA: 3745.08,4257.38 3735.08,4257.38 cw(c3674.92,4257.38) 3733.18,4242.38 3746.98,4242.38 cw(c3805.24,4257.38)
  region net $1N1534: 3552.16,4257.38 3542.16,4257.38 cw(c3434.97,4257.38) 3541.11,4242.38 3553.22,4242.38 cw(c3659.36,4257.38)
  region net $1N1817: 3524.6,4257.38 3514.6,4257.38 cw(c3407.41,4257.38) 3513.55,4242.38 3525.66,4242.38 cw(c3631.8,4257.38)
  region net $1N1822: 3497.24,4257.32 3487.24,4257.32 cw(c3427.08,4257.32) 3485.34,4242.32 3499.14,4242.32 cw(c3557.4,4257.32)
  region net $1N1393: 4233.39,4333.09 4243.39,4333.09 cw(c4252.85,4333.09) 4250.89,4342.34 4225.89,4342.34 cw(c4223.93,4333.09)
  region net $1N1215: 4257.67,4386.85 4266.71,4391.96 cw(c4293.23,4418.47) 4256.1,4413.17 4236.46,4397.46 cw(c4231.16,4360.34)
  region net $1N1397: 4159.27,4327.34 4169.27,4327.34 cw(c4188.02,4327.34) 4176.77,4342.34 4151.77,4342.34 cw(c4140.52,4327.34)
  region net $1N1238: 4189.4,4386.85 4192.59,4397.81 cw(c4219.11,4424.32) 4181.98,4419.02 4168.19,4397.46 cw(c4162.89,4360.34)
  region net $1N1534: 3565.35,4333.25 3573.56,4327.31 cw(c3600.07,4300.8) 3594.77,4337.92 3575.96,4354.46 cw(c3538.84,4359.77)
  region net SDA: 3673.94,4327.31 3686.6,4328.8 cw(c3713.12,4355.32) 3675.99,4350.01 3652.73,4337.92 cw(c3647.43,4300.8)
  region net VCC: 3690.99,4408.11 3690.99,4418.11 cw(c3690.99,4436.86) 3675.99,4425.61 3675.99,4400.61 cw(c3690.99,4389.36)
  region net SCL: 3720,4322.92 3730,4322.92 cw(c3748.75,4322.92) 3737.5,4337.92 3712.5,4337.92 cw(c3701.25,4322.92)
  region net VCC: 3692.99,4418.11 3692.99,4408.11 cw(c3692.99,4389.36) 3707.99,4400.61 3707.99,4425.61 cw(c3692.99,4436.86)
  region net VCC: 3724.66,4443.99 3714.66,4443.99 cw(c3694.45,4443.99) 3707.99,4428.99 3732.16,4428.99 cw(c3743.41,4443.99)
  region net $1N1817: 3514.6,4327.95 3524.6,4327.95 cw(c3543.35,4327.95) 3532.1,4342.95 3507.1,4342.95 cw(c3495.85,4327.95)
  region net $1N1822: 3468.17,4332.34 3477.21,4337.45 cw(c3503.72,4363.96) 3466.6,4358.66 3446.96,4342.95 cw(c3441.65,4305.83)
  region net VCC: 4057.64,4363.7 4057.64,4353.7 cw(c4057.64,4334.95) 4072.64,4346.2 4072.64,4371.2 cw(c4057.64,4382.45)
  region net VCC: 4118.68,4379.95 4109.64,4385.05 cw(c4083.13,4411.57) 4088.43,4374.45 4108.08,4358.74 cw(c4145.2,4353.43)
  region net VCC: 4085.36,4327.95 4095.36,4327.95 cw(c4114.11,4327.95) 4102.86,4342.95 4077.86,4342.95 cw(c4066.61,4327.95)
  region net VCC: 3987.92,4338.31 3996.09,4332.34 cw(c4022.6,4305.83) 4017.3,4342.95 3998.52,4359.53 cw(c3961.4,4364.83)
  region net VCC: 4048.95,4353.7 4048.95,4363.7 cw(c4048.95,4382.45) 4033.95,4371.2 4033.95,4346.2 cw(c4048.95,4334.95)
  region net VCC: 3899.56,4433.66 3891.35,4439.6 cw(c3864.84,4466.11) 3870.14,4428.99 3888.95,4412.44 cw(c3926.07,4407.14)
  region net VCC: 3852.53,4439.6 3844.33,4433.66 cw(c3817.81,4407.14) 3854.93,4412.44 3873.74,4428.99 cw(c3879.05,4466.11)
  region net $1N3071: 3872.87,4322.92 3882.87,4322.92 cw(c3904.42,4322.92) 3888.95,4337.92 3865.37,4337.92 cw(c3854.12,4322.92)
  region net $1N3071: 3839.93,4356.7 3839.93,4346.7 cw(c3839.93,4327.95) 3854.93,4339.2 3854.93,4364.2 cw(c3839.93,4375.45)
  region net $1N3071: 3903.95,4348.79 3903.95,4358.79 cw(c3903.95,4377.54) 3888.95,4366.29 3888.95,4341.29 cw(c3903.95,4330.04)
  region net VCC: 3714.66,4461.32 3724.66,4461.32 cw(c3743.41,4461.32) 3732.16,4476.32 3707.16,4476.32 cw(c3695.91,4461.32)
  region net VCC: 3750.54,4488.33 3750.54,4498.33 cw(c3750.54,4517.08) 3735.54,4505.83 3735.54,4480.83 cw(c3750.54,4469.58)
  region net VCC: 3699.12,4520.94 3693.18,4512.74 cw(c3666.66,4486.22) 3703.78,4491.52 3720.33,4510.33 cw(c3725.63,4547.46)
  region net $1N3071: 3837.64,4346.7 3837.64,4356.7 cw(c3837.64,4375.45) 3822.64,4364.2 3822.64,4339.2 cw(c3837.64,4327.95)
  region net VCC: 3822.34,4455.65 3833.24,4458.88 cw(c3859.76,4485.4) 3822.64,4480.1 3801.12,4466.26 cw(c3795.82,4429.13)
  region net VCC: 3762.36,4498.33 3762.36,4488.33 cw(c3762.36,4469.58) 3777.36,4480.83 3777.36,4503.66 cw(c3762.36,4522.1)
  region net $1N3071: 3909.4,4358.79 3909.4,4348.79 cw(c3909.4,4241.6) 3924.4,4347.74 3924.4,4366.29 cw(c3909.4,4377.54)
  region net $1N3221: 3614.5,4467.83 3619.02,4474.62 cw(c3640.23,4495.84) 3610.54,4491.59 3597.53,4476.32 cw(c3593.28,4446.62)
  region net VCC: 3344.37,4389.51 3334.37,4389.51 cw(c3315.62,4389.51) 3326.87,4374.51 3351.87,4374.51 cw(c3363.12,4389.51)
  region net 3V3: 3270.63,4367.11 3250.63,4367.11 cw(c3212.52,4367.11) 3236.02,4337.11 3285.24,4337.11 cw(c3308.74,4367.11)
  region net 3V3: 3250.63,4279.55 3270.63,4279.55 cw(c3308.74,4279.55) 3285.24,4309.55 3236.02,4309.55 cw(c3212.52,4279.55)
  region net 3V3: 3294.25,4254.08 3274.25,4254.08 cw(c3147.44,4254.08) 3272.14,4231.04 3296.36,4231.04 cw(c3421.06,4254.08)
  region net +5V: 4886.26,4834.59 4906.26,4834.59 4906.3,4835.6 4906.35,4836 4906.42,4836.35 4906.51,4836.65 4906.63,4836.9 4906.77,4837.12 4906.94,4837.3 4907.14,4837.46 4907.36,4837.6 4907.61,4837.72 4908.92,4838.24 4909.77,4838.6 4910.77,4839.09 4911.92,4839.77 4913.22,4840.69 4914.69,4841.9 4916.33,4843.45 4918.16,4845.4 4921.26,4849.17 4871.26,4849.17 4873.87,4845.95 4875.75,4843.9 4877.44,4842.25 4878.59,4841.26 4879.64,4840.44 4880.6,4839.77 4881.48,4839.24 4882.27,4838.83 4883.19,4838.41 4884.63,4837.85 4884.91,4837.72 4885.16,4837.6 4885.27,4837.53 4885.38,4837.46 4885.48,4837.38 4885.58,4837.3 4885.66,4837.21 4885.75,4837.12 4885.82,4837.01 4885.89,4836.9 4885.95,4836.78 4886.01,4836.65 4886.06,4836.51 4886.1,4836.35 4886.17,4836 4886.22,4835.6 4886.26,4834.87
  region net $1N12056: 4907.43,4275.61 4917.43,4275.61 cw(c4936.18,4275.61) 4924.93,4290.61 4899.93,4290.61 cw(c4888.68,4275.61)
  region net $1N12056: 4917.43,4341.04 4907.43,4341.04 cw(c4888.68,4341.04) 4899.93,4326.04 4924.93,4326.04 cw(c4936.18,4341.04)
  region net 3V3: 4249.76,4607.09 4249.76,4637.09 cw(c4249.76,4747.33) 4204.76,4646.7 4204.76,4603.39 cw(c4249.76,4331.89)
  region net 3V3: 3845.63,4635.04 3845.63,4615.04 cw(c3845.63,4577.54) 3875.63,4600.04 3875.63,4650.04 cw(c3845.63,4672.54)
  region net 3V3: 4322.04,4612.09 4322.04,4632.09 cw(c4322.04,4713.26) 4292.04,4637.84 4292.04,4606.34 cw(c4322.04,4530.93)
  region net 3V3: 4211.61,4637.09 4211.61,4607.09 ccw(c4211.61,4773.22) 4256.61,4613.3 4256.61,4630.88 ccw(c4211.61,4470.97)
  region net +5V: 4317.04,4696.97 4317.04,4716.97 cw(c4317.04,4798.14) 4287.04,4722.72 4287.04,4691.22 cw(c4317.04,4615.81)
  region net +5V: 4099.71,4895.69 4093.92,4887.34 cw(c4067.4,4860.82) 4104.52,4866.13 4120.92,4885.08 cw(c4126.22,4922.21)
  region net $1N12056: 4877.49,4383.66 4877.49,4373.66 cw(c4877.49,4354.91) 4892.49,4366.16 4892.49,4391.16 cw(c4877.49,4402.41)
  region net $1N12056: 4907.43,4346.65 4917.43,4346.65 cw(c4937.37,4346.65) 4924.24,4361.65 4899.93,4361.65 cw(c4888.68,4346.65)
  region net $1N12056: 4917.43,4270.53 4907.43,4270.53 cw(c4888.68,4270.53) 4899.93,4255.53 4924.24,4255.53 cw(c4937.37,4270.53)
  region net $1N4419: 4998.56,4233.53 4998.56,4243.53 cw(c4998.56,4262.28) 4983.56,4251.03 4983.56,4226.03 cw(c4998.56,4214.78)
  region net VOUT: 4440.16,4223.38 4454.5,4237.32 cw(c4507.53,4290.35) 4433.28,4279.75 4397.73,4244.59 cw(c4387.12,4170.34)
  region net VOUT: 4344.91,4346.9 4330.57,4332.96 cw(c4277.54,4279.93) 4351.79,4290.53 4387.34,4325.69 cw(c4397.95,4399.94)
  region net $1N4369: 4726.49,4076.41 4735.9,4081.15 cw(c4762.41,4107.67) 4725.29,4102.36 4705.28,4087.02 cw(c4699.98,4049.9)
  region net $1N4372: 4840.29,4103.33 4840.29,4113.33 cw(c4840.29,4132.08) 4825.29,4120.83 4825.29,4095.83 cw(c4840.29,4084.58)
  region net $1N12056: 4835.9,4354.99 4835.9,4369.13 cw(c4821.48,4383.54) 4819.42,4363.26 4825.29,4333.77 cw(c4862.41,4328.47)
  region net IO33: 3303.25,4768 3310.32,4775.07 3309.69,4775.79 3309.17,4776.56 3308.75,4777.37 3308.44,4778.23 3308.21,4779.14 3308.07,4780.08 3308.02,4781.06 3308.03,4782.08 3308.12,4783.13 3308.47,4785.3 3309.02,4787.57 3310.12,4791.1 3313.46,4800.68 3314.13,4803 3314.63,4805.23 3314.8,4806.32 3314.92,4807.37 3314.96,4808.4 3314.94,4809.39 3283.12,4777.57 3284.33,4777.45 3285.6,4777.23 3286.92,4776.92 3288.97,4776.31 3291.07,4775.54 3293.17,4774.63 3295.24,4773.61 3297.24,4772.49 3299.12,4771.31 3300.84,4770.08 3302.37,4768.84
  region net IO32: 3317.42,4911.6 3310.34,4918.67 3309.06,4917.46 3308.23,4916.77 3307.43,4916.18 3306.64,4915.66 3305.87,4915.23 3305.11,4914.86 3304.37,4914.57 3303.64,4914.34 3302.91,4914.18 3302.18,4914.07 3301.46,4914 3300.74,4913.99 3300.02,4914.02 3298.92,4914.12 3297.42,4914.37 3292.53,4915.43 3290.22,4915.85 3288.22,4916.11 3286.62,4916.22 3284.92,4916.25 3283.12,4916.19 3314.94,4884.37 3315,4886.17 3314.97,4887.87 3314.8,4889.99 3314.53,4891.95 3313.9,4895.08 3313.05,4899.05 3312.87,4900.17 3312.77,4901.27 3312.74,4901.99 3312.75,4902.71 3312.81,4903.43 3312.93,4904.16 3313.09,4904.89 3313.32,4905.62 3313.61,4906.36 3313.97,4907.12 3314.41,4907.89 3314.93,4908.68 3315.52,4909.48 3316.21,4910.31
  region net +5V: 3368.74,4848.35 3358.74,4848.35 3358.68,4846.59 3358.58,4845.52 3358.44,4844.53 3358.25,4843.61 3358.01,4842.76 3357.73,4841.97 3357.41,4841.23 3357.05,4840.55 3356.66,4839.92 3356.22,4839.33 3355.76,4838.78 3355.26,4838.26 3354.73,4837.76 3353.87,4837.06 3352.64,4836.18 3348.43,4833.47 3346.5,4832.14 3344.91,4830.9 3343.69,4829.85 3342.47,4828.67 3341.24,4827.35 3386.24,4827.35 3385.01,4828.67 3383.79,4829.85 3382.17,4831.23 3380.59,4832.42 3377.94,4834.19 3374.52,4836.39 3373.61,4837.06 3372.75,4837.76 3372.22,4838.26 3371.72,4838.78 3371.26,4839.33 3370.82,4839.92 3370.43,4840.55 3370.07,4841.23 3369.75,4841.97 3369.47,4842.76 3369.23,4843.61 3369.04,4844.53 3368.9,4845.52 3368.8,4846.59
  region net +5V: 3358.74,4841.25 3368.74,4841.25 cw(c3387.49,4841.25) 3376.24,4856.25 3351.24,4856.25 cw(c3339.99,4841.25)
  region net SDA: 3705,4281.99 3715,4281.99 3715.02,4282.56 3715.09,4283.13 3715.2,4283.69 3715.34,4284.26 3715.52,4284.82 3715.98,4285.93 3716.54,4287.01 3717.19,4288.05 3717.89,4289.03 3719,4290.39 3701,4290.39 3702.11,4289.03 3702.81,4288.05 3703.46,4287.01 3704.02,4285.93 3704.48,4284.82 3704.66,4284.26 3704.8,4283.69 3704.91,4283.13 3704.98,4282.56
  region net SDA: 3718.02,4283.24 3725.09,4290.31 3724.7,4290.73 3724.35,4291.18 3724.02,4291.65 3723.73,4292.16 3723.46,4292.68 3723,4293.79 3722.63,4294.95 3722.35,4296.14 3722.15,4297.33 3721.98,4299.08 3709.25,4286.35 3711,4286.18 3712.19,4285.98 3713.38,4285.7 3714.54,4285.33 3715.64,4284.87 3716.17,4284.6 3716.67,4284.3 3717.15,4283.98 3717.6,4283.62
  region net SDA: 3701.98,4313.41 3694.91,4306.34 3695.3,4305.93 3695.65,4305.48 3695.98,4305 3696.27,4304.5 3696.54,4303.97 3697,4302.86 3697.37,4301.7 3697.65,4300.52 3697.85,4299.32 3698.02,4297.57 3710.75,4310.3 3709,4310.48 3707.81,4310.68 3706.62,4310.96 3705.46,4311.32 3704.36,4311.78 3703.83,4312.05 3703.33,4312.35 3702.85,4312.67 3702.4,4313.03
  region net SCL: 3761.98,4288.41 3754.91,4281.34 3755.3,4280.93 3755.65,4280.48 3755.98,4280 3756.27,4279.5 3756.54,4278.97 3757,4277.86 3757.37,4276.7 3757.65,4275.52 3757.85,4274.32 3758.02,4272.57 3770.75,4285.3 3769,4285.48 3767.81,4285.68 3766.62,4285.96 3765.46,4286.32 3764.36,4286.78 3763.83,4287.05 3763.33,4287.35 3762.85,4287.67 3762.4,4288.03
  region net SCL: 3765,4256.99 3775,4256.99 3775.02,4257.56 3775.09,4258.13 3775.2,4258.69 3775.34,4259.26 3775.52,4259.82 3775.98,4260.93 3776.54,4262.01 3777.19,4263.05 3777.89,4264.03 3779,4265.39 3761,4265.39 3762.11,4264.03 3762.81,4263.05 3763.46,4262.01 3764.02,4260.93 3764.48,4259.82 3764.66,4259.26 3764.8,4258.69 3764.91,4258.13 3764.98,4257.56
  region net V_USB: 5020,4428.75 5000,4428.75 5000.07,4427.13 5000.4,4424.33 5000.5,4423.07 5000.51,4422.47 5000.47,4421.87 5000.37,4421.28 5000.21,4420.69 4999.98,4420.09 4999.67,4419.49 4999.26,4418.88 4998.75,4418.25 5021.25,4418.25 5020.74,4418.88 5020.33,4419.49 5020.02,4420.09 5019.79,4420.69 5019.63,4421.28 5019.53,4421.87 5019.49,4422.47 5019.5,4423.07 5019.6,4424.33 5019.93,4427.13
  region net V_USB: 4988.49,4400.96 5002.63,4386.82 5003.72,4388.01 5005.48,4390.22 5006.29,4391.18 5006.71,4391.61 5007.17,4392.01 5007.65,4392.36 5008.18,4392.67 5008.76,4392.92 5009.41,4393.12 5010.13,4393.27 5010.94,4393.36 4995.03,4409.27 4994.94,4408.46 4994.8,4407.74 4994.6,4407.09 4994.34,4406.51 4994.03,4405.98 4993.68,4405.49 4993.29,4405.04 4992.86,4404.62 4991.89,4403.8 4989.68,4402.05
  region net V_USB: 5000,4532.9 5020,4532.9 5019.93,4534.52 5019.6,4537.32 5019.5,4538.58 5019.49,4539.19 5019.53,4539.78 5019.63,4540.38 5019.79,4540.97 5020.02,4541.56 5020.33,4542.16 5020.74,4542.78 5021.25,4543.4 4998.75,4543.4 4999.26,4542.78 4999.67,4542.16 4999.98,4541.56 5000.21,4540.97 5000.37,4540.38 5000.47,4539.78 5000.51,4539.19 5000.5,4538.58 5000.4,4537.32 5000.07,4534.52
  region net $1N4419: 5030.48,4233.41 5023.41,4226.34 5023.8,4225.93 5024.15,4225.48 5024.48,4225 5024.77,4224.5 5025.04,4223.97 5025.5,4222.86 5025.87,4221.7 5026.15,4220.52 5026.35,4219.32 5026.52,4217.57 5039.25,4230.3 5037.5,4230.48 5036.31,4230.68 5035.12,4230.96 5033.96,4231.32 5032.86,4231.78 5032.33,4232.05 5031.83,4232.35 5031.35,4232.67 5030.9,4233.03
  region net $1N4369: 4893.66,4053.33 4893.66,4043.33 4894.23,4043.3 4894.8,4043.24 4895.37,4043.13 4895.93,4042.98 4896.49,4042.8 4897.6,4042.35 4898.68,4041.78 4899.72,4041.14 4900.7,4040.44 4902.06,4039.33 4902.06,4057.33 4900.7,4056.21 4899.72,4055.51 4898.68,4054.87 4897.6,4054.31 4896.49,4053.85 4895.93,4053.67 4895.37,4053.52 4894.8,4053.42 4894.23,4053.35
  region net $1N4372: 4903.66,4113.33 4903.66,4103.33 4904.23,4103.3 4904.8,4103.24 4905.37,4103.13 4905.93,4102.98 4906.49,4102.8 4907.6,4102.35 4908.68,4101.78 4909.72,4101.14 4910.7,4100.44 4912.06,4099.33 4912.06,4117.33 4910.7,4116.21 4909.72,4115.51 4908.68,4114.87 4907.6,4114.31 4906.49,4113.85 4905.93,4113.67 4905.37,4113.52 4904.8,4113.42 4904.23,4113.35
  region net +5V: 4420,4643.75 4400,4643.75 4400.07,4642.13 4400.4,4639.33 4400.5,4638.07 4400.51,4637.47 4400.47,4636.87 4400.37,4636.28 4400.21,4635.69 4399.98,4635.09 4399.67,4634.49 4399.26,4633.88 4398.75,4633.25 4421.25,4633.25 4420.74,4633.88 4420.33,4634.49 4420.02,4635.09 4419.79,4635.69 4419.63,4636.28 4419.53,4636.87 4419.49,4637.47 4419.5,4638.07 4419.6,4639.33 4419.93,4642.13
  region net 3V3: 3358.49,4560.96 3372.63,4546.82 3373.72,4548.01 3375.48,4550.22 3376.29,4551.18 3376.71,4551.61 3377.17,4552.01 3377.65,4552.36 3378.18,4552.67 3378.76,4552.92 3379.41,4553.12 3380.13,4553.27 3380.94,4553.36 3365.03,4569.27 3364.94,4568.46 3364.8,4567.74 3364.6,4567.09 3364.34,4566.51 3364.03,4565.98 3363.68,4565.49 3363.29,4565.04 3362.86,4564.62 3361.89,4563.8 3359.68,4562.05
  region net 3V3: 3400.42,4558.33 3400.42,4578.33 3398.81,4578.26 3396,4577.93 3394.75,4577.83 3394.14,4577.82 3393.54,4577.86 3392.95,4577.96 3392.36,4578.11 3391.77,4578.35 3391.16,4578.66 3390.55,4579.07 3389.92,4579.58 3389.92,4557.08 3390.55,4557.59 3391.16,4557.99 3391.77,4558.31 3392.36,4558.54 3392.95,4558.7 3393.54,4558.79 3394.14,4558.83 3394.75,4558.83 3396,4558.72 3398.81,4558.4
  region net EN: 3799.91,4745.31 3806.98,4738.24 3807.4,4738.62 3807.85,4738.98 3808.33,4739.3 3808.83,4739.6 3809.36,4739.87 3810.46,4740.33 3811.62,4740.7 3812.81,4740.98 3814,4741.18 3815.75,4741.35 3803.02,4754.08 3802.85,4752.33 3802.65,4751.14 3802.37,4749.95 3802,4748.79 3801.54,4747.68 3801.27,4747.16 3800.98,4746.65 3800.65,4746.18 3800.3,4745.73
  region net EN: 3376.34,4623.33 3376.34,4633.33 3375.77,4633.35 3375.2,4633.42 3374.63,4633.52 3374.07,4633.67 3373.51,4633.85 3372.4,4634.31 3371.32,4634.87 3370.28,4635.51 3369.3,4636.21 3367.94,4637.33 3367.94,4619.33 3369.3,4620.44 3370.28,4621.14 3371.32,4621.78 3372.4,4622.35 3373.51,4622.8 3374.07,4622.98 3374.63,4623.13 3375.2,4623.24 3375.77,4623.3
  region net IO32: 3676.98,4733.41 3669.91,4726.34 3670.3,4725.93 3670.65,4725.48 3670.98,4725 3671.27,4724.5 3671.54,4723.97 3672,4722.86 3672.37,4721.7 3672.65,4720.52 3672.85,4719.32 3673.02,4717.57 3685.75,4730.3 3684,4730.48 3682.81,4730.68 3681.62,4730.96 3680.46,4731.32 3679.36,4731.78 3678.83,4732.05 3678.33,4732.35 3677.85,4732.67 3677.4,4733.03
  region net IO33: 3641.98,4708.41 3634.91,4701.34 3635.3,4700.93 3635.65,4700.48 3635.98,4700 3636.27,4699.5 3636.54,4698.97 3637,4697.86 3637.37,4696.7 3637.65,4695.52 3637.85,4694.32 3638.02,4692.57 3650.75,4705.3 3649,4705.48 3647.81,4705.68 3646.62,4705.96 3645.46,4706.32 3644.36,4706.78 3643.83,4707.05 3643.33,4707.35 3642.85,4707.67 3642.4,4708.03
  region net 3V3: 4304.58,4632.09 4304.58,4612.09 4305.52,4612.13 4306.37,4612.23 4307.16,4612.39 4308.54,4612.79 4310.32,4613.38 4310.87,4613.52 4311.41,4613.6 4311.96,4613.62 4312.52,4613.54 4313.1,4613.37 4313.71,4613.07 4314.37,4612.65 4315.08,4612.08 4315.08,4634.58 4314.53,4634.13 4313.96,4633.74 4313.37,4633.4 4312.76,4633.12 4312.14,4632.87 4311.5,4632.67 4310.85,4632.51 4309.51,4632.28 4308.14,4632.16
  region net +5V: 3570.42,4918.33 3570.42,4928.33 3569.56,4928.36 3568.76,4928.47 3568,4928.64 3567.29,4928.86 3566.61,4929.15 3565.96,4929.48 3565.33,4929.86 3564.73,4930.28 3563.56,4931.23 3560.57,4933.99 3559.92,4934.58 3559.92,4912.08 3562.98,4914.91 3564.14,4915.92 3564.73,4916.37 3565.33,4916.79 3565.96,4917.17 3566.61,4917.51 3567.29,4917.79 3568,4918.02 3568.76,4918.19 3569.56,4918.29
  region net $1N3071: 3884.38,4348.79 3874.38,4353.79 3857.4,4346.7 3857.4,4356.7 3867.4,4351.7 3884.38,4358.79
  region net VCC: 4103.54,4301.86 4102.69,4302.78 4101.87,4303.82 4101.08,4304.95 4099.97,4306.82 4098.94,4308.84 4098.02,4310.98 4097.21,4313.17 4096.53,4315.39 4095.99,4317.59 4095.61,4319.71 4095.45,4321.06 4095.37,4322.35 4095.36,4322.97 4085.36,4322.97 4085.3,4322.03 4085.13,4321.1 4084.87,4320.19 4084.5,4319.3 4084.05,4318.43 4083.51,4317.61 4082.91,4316.82 4082.23,4316.09 4081.5,4315.42 4080.72,4314.81 4079.89,4314.28 4079.03,4313.83 4078.14,4313.46 4077.22,4313.19 4076.3,4313.02 4075.36,4312.97 4075.36,4302.97 4076.61,4302.93 4077.93,4302.8 4080.02,4302.48 4082.2,4301.99 4084.41,4301.36 4086.62,4300.59 4088.78,4299.71 4090.85,4298.71 4092.77,4297.62 4093.95,4296.85 4095.04,4296.05 4096.02,4295.22 4096.46,4294.79
  region net VCC: 4081.2,4355.16 4082,4354.29 4082.69,4353.38 4083.28,4352.44 4083.78,4351.47 4084.19,4350.48 4084.52,4349.45 4084.79,4348.4 4084.99,4347.33 4085.2,4345.68 4085.34,4343.41 4085.36,4338.07 4095.36,4338.07 4090.36,4348.07 4088.27,4362.23
  region net $1N3221: 3622.17,4471.47 3615.34,4466.99 ccw(c3629.39,4481.04) 3621,4463.03 3624.96,4466.99 ccw(c3613.95,4463.25)
  region net $1N3221: 3633.81,4471.14 3625.33,4468.31 3628.16,4476.8
  region net V_USB: 4985.86,4398.33 5002.93,4387.11 ccw(c4982.38,4407.66) 5009.9,4398.33 5000,4408.23 ccw(c5020.98,4363.2)
  region net 3V3: 3358.79,4561.26 3370,4544.18 ccw(c3334.88,4579.31) 3379.9,4558.33 3370,4568.23 ccw(c3379.33,4540.71)
  region net +5V: 4420,4636.97 4400,4636.97 ccw(c4300,4636.97) 4380,4696.97 4440,4696.97 ccw(c4520,4636.97)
